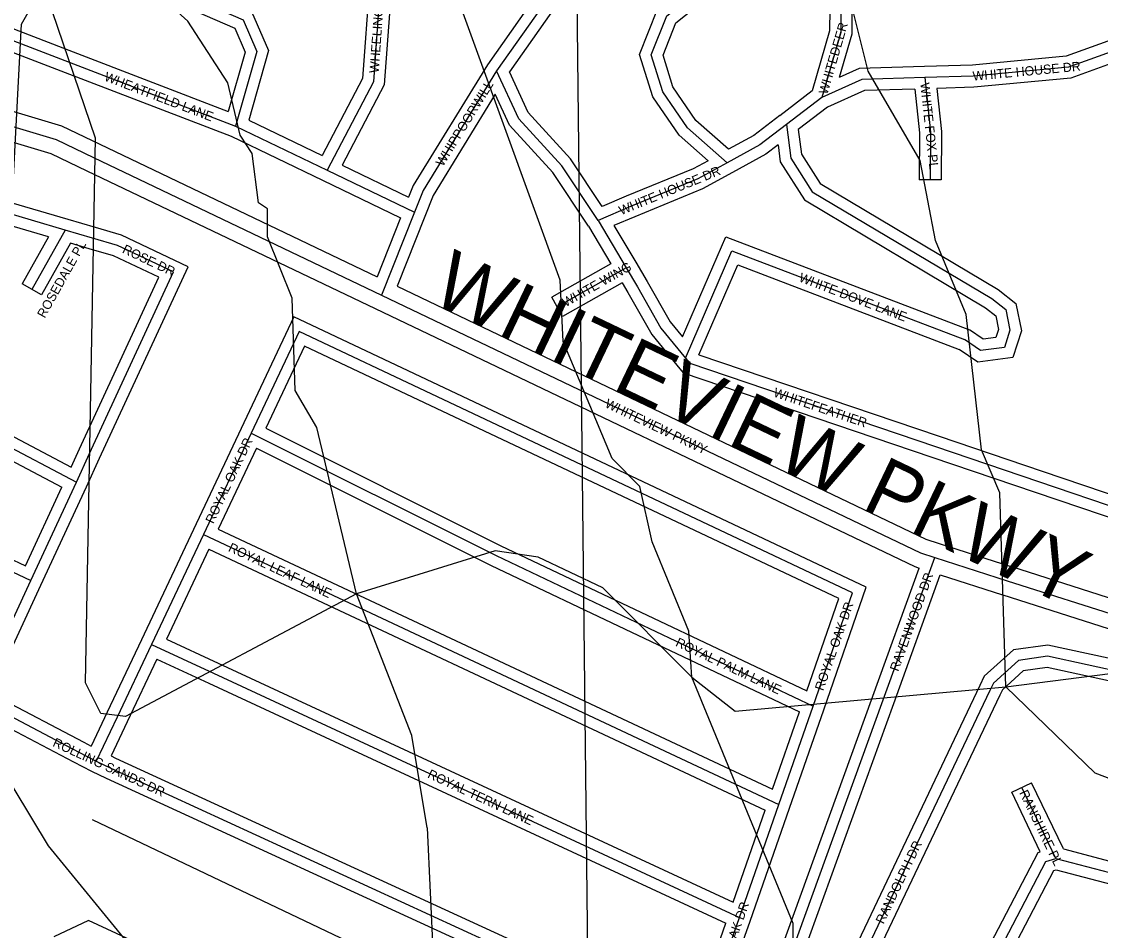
# Model space of a CAD drawing. Extents: x 457167 to 656239, y 1787309 to 1969297.
# Drawn here: x 578435 to 581357, y 1883556 to 1886017 of the extents above; entities that cross this region are included whole.
import ezdxf

# ---------------------------------------------------------------- set-up
doc = ezdxf.new("R2010")
doc.units = 0
for name, color, linetype in [('Level 1', 7, 'Continuous'), ('Level 22', 7, 'Continuous'), ('Level 23', 7, 'Continuous'), ('Level 28', 7, 'Continuous'), ('Level 31', 7, 'Continuous'), ('Level 32', 7, 'Continuous'), ('Level 34', 7, 'Continuous'), ('Level 5', 7, 'Continuous'), ('Level 7', 7, 'Continuous')]:
    doc.layers.add(name, color=color, linetype=linetype)

msp = doc.modelspace()

# ---------------------------------------------------------------- linework, layer by layer
at = {"layer": 'Level 1'}
msp.add_line((579922.889, 1887536.016), (579980.794, 1882300.366), dxfattribs=at)
at = {"layer": 'Level 22'}
for p, q in [((578629.542, 1885649.562), (579410.25, 1885276.297)), ((580908.17, 1884565.946), (581104.294, 1884503.001)), ((581104.294, 1884503.001), (581592.856, 1884347.106))]:
    msp.add_line(p, q, dxfattribs=at)
for points in [[(577109.898, 1886124.416), (578528.818, 1885697.774), (578629.542, 1885649.562)], [(579410.25, 1885276.297), (580869.39, 1884578.388), (580908.17, 1884565.946)]]:
    msp.add_lwpolyline(points, dxfattribs=at)
at = {"layer": 'Level 23'}
for p, q in [((578646.796, 1885685.651), (579397.924, 1885326.527)), ((578612.289, 1885613.474), (579392.997, 1885240.209)), ((580920.394, 1884604.032), (581116.517, 1884541.089)), ((581116.453, 1884541.11), (581605.016, 1884385.213)), ((580923.139, 1884519.131), (581092.07, 1884464.914)), ((581092.134, 1884464.893), (581580.698, 1884308.997))]:
    msp.add_line(p, q, dxfattribs=at)
for points in [[(577146.313, 1886155.236), (578543.298, 1885735.19), (578646.812, 1885685.643)], [(577102.36, 1886084.911), (578514.338, 1885660.358), (578612.273, 1885613.481)], [(579452.18, 1885300.582), (580884.199, 1884615.646), (580920.391, 1884604.034)], [(579392.991, 1885240.211), (580854.583, 1884541.13), (580865.97, 1884537.476)]]:
    msp.add_lwpolyline(points, dxfattribs=at)
at = {"layer": 'Level 31'}
for p, q in [((580024.011, 1886313.221), (579721.612, 1885884.022)), ((578564.242, 1885907.519), (579014.892, 1885734.576)), ((580602.173, 1885811.669), (580506.606, 1885738.773)), ((579014.892, 1885734.576), (579262.732, 1885614.787)), ((579262.732, 1885614.787), (579499.453, 1885500.841)), ((578553.114, 1885452.63), (578246.373, 1885542.73)), ((579499.453, 1885500.841), (579410.25, 1885276.297)), ((579996.223, 1885479.09), (580072.614, 1885350.568)), ((578553.114, 1885452.63), (578463.085, 1885292.091)), ((578626.86, 1885431.021), (578553.114, 1885452.63)), ((578619.282, 1884847.396), (578846.769, 1885339.288)), ((580072.614, 1885350.568), (579885.693, 1885245.133)), ((579186.765, 1885178.215), (579057.059, 1884902.846)), ((580685.644, 1884470.035), (579186.765, 1885178.215)), ((579057.059, 1884902.846), (578927.99, 1884628.568)), ((579057.059, 1884902.846), (579720.185, 1884570.924)), ((580910.051, 1884866.308), (581189.442, 1884771.559)), ((578583.496, 1884769.652), (578619.282, 1884847.396)), ((578460.484, 1884503.726), (578583.496, 1884769.652)), ((581189.442, 1884771.559), (581477.098, 1884673.886)), ((578927.99, 1884628.568), (578787.418, 1884329.95)), ((578927.99, 1884628.568), (579322.65, 1884443.018)), ((579720.185, 1884570.924), (580099.594, 1884390.869)), ((580768.71, 1884180.409), (580908.17, 1884565.946)), ((578312.549, 1884184.761), (578460.484, 1884503.726)), ((580579.103, 1884163.34), (580685.644, 1884470.035)), ((579322.65, 1884443.018), (580486.319, 1883896.982)), ((580099.594, 1884390.869), (580579.103, 1884163.34)), ((578787.418, 1884329.95), (578694.45, 1884133.779)), ((578787.418, 1884329.95), (578954.564, 1884252.51)), ((578954.564, 1884252.51), (580379.777, 1883591.016)), ((578312.549, 1884184.761), (578589.924, 1884039.087)), ((580465.153, 1883342.84), (580768.71, 1884180.409)), ((580486.319, 1883896.982), (580579.103, 1884163.34)), ((578694.45, 1884133.779), (578637.582, 1884013.896)), ((578589.924, 1884039.087), (578637.582, 1884013.896)), ((578637.582, 1884013.896), (578676.986, 1883995.632)), ((578676.986, 1883995.632), (580265.558, 1883265.43)), ((581235.733, 1883751.094), (581143.559, 1883942.918)), ((580379.777, 1883591.016), (580486.319, 1883896.982)), ((581235.733, 1883751.094), (581870.919, 1883583.996)), ((580318.989, 1883418.048), (580379.777, 1883591.016))]:
    msp.add_line(p, q, dxfattribs=at)
for points in [[(577879.429, 1886195.146), (577932.779, 1886155.396), (577988.45, 1886160.732), (578387.86, 1885975.162), (578564.242, 1885907.519)], [(578645.304, 1886192.08), (579035.208, 1886022.173), (579072.244, 1885936.641), (579014.892, 1885734.576)], [(580346.093, 1885635.101), (580238.462, 1885729.503), (580171.869, 1885827.095), (580140.586, 1885927.524), (580182.467, 1886032.893), (580294.607, 1886122.846), (580409.238, 1886186.611), (580467.765, 1886189.037), (580579.053, 1886173.174), (580654.66, 1886128.656), (580653.419, 1885987.566), (580602.173, 1885811.669)], [(579408.533, 1886139.216), (579387.907, 1885854.53), (579262.732, 1885614.787)], [(581522.66, 1885980.713), (581475.88, 1885968.443), (581270.264, 1885893.949), (581012.269, 1885869.745), (580880.903, 1885865.647)], [(579721.612, 1885884.022), (579522.793, 1885559.702), (579499.453, 1885500.841)], [(579996.223, 1885479.09), (579897.926, 1885626.93), (579782.094, 1885754.078), (579721.612, 1885884.022)], [(580880.903, 1885865.647), (580710.73, 1885860.539), (580602.173, 1885811.669)], [(580880.903, 1885865.647), (580896.825, 1885717.977), (580895.609, 1885588.888)], [(580506.606, 1885738.773), (580434.294, 1885684.011), (580346.093, 1885635.101)], [(580506.606, 1885738.773), (580518.825, 1885647.838), (580576.527, 1885556.447), (581062.579, 1885267.092), (581100.368, 1885237.197), (581111.706, 1885181.537), (581096.662, 1885134.659), (581032.078, 1885126.426), (580988.563, 1885155.969)], [(580346.093, 1885635.101), (580266.487, 1885591.263), (580084.403, 1885516.727), (579996.223, 1885479.09)], [(578846.769, 1885339.288), (578695.203, 1885411.241), (578626.86, 1885431.021)], [(580232.736, 1885106.237), (580358.329, 1885396.528), (580988.563, 1885155.969)], [(580072.614, 1885350.568), (580103.041, 1885298.868), (580166.425, 1885186.738), (580232.736, 1885106.237)], [(576976.576, 1885202.511), (577734.242, 1885217.989), (578583.496, 1884769.652)], [(580232.736, 1885106.237), (580244.476, 1885092.031), (580910.051, 1884866.308)], [(576991.504, 1884893.021), (577643.854, 1884889.087), (578460.484, 1884503.726)], [(581428.539, 1884251.436), (581213.616, 1884298.416), (581134.711, 1884287.302), (581066.837, 1884225.985), (581057.574, 1884206.003)], [(581057.574, 1884206.003), (580549.346, 1883137.939), (580555.006, 1883105.564), (580566.367, 1883061.541), (580699.668, 1882916.177), (580763.226, 1882886.956)], [(580763.226, 1882886.956), (581209.315, 1883742.421), (581235.733, 1883751.094)]]:
    msp.add_lwpolyline(points, dxfattribs=at)
at = {"layer": 'Level 32'}
for p, q in [((579987.384, 1886313.321), (579696.536, 1885900.518)), ((580046.989, 1886293.744), (579756.139, 1885880.937)), ((578574.991, 1885935.527), (578994.995, 1885774.345)), ((578553.494, 1885879.511), (579002.97, 1885707.017)), ((580576.132, 1885829.536), (580488.412, 1885762.626)), ((580617.629, 1885785.726), (580538.661, 1885725.491)), ((579050.633, 1885750.622), (579249.601, 1885654.455)), ((579002.969, 1885707.017), (579249.677, 1885587.776)), ((579303.671, 1885628.376), (579483.439, 1885541.845)), ((578561.569, 1885481.414), (578254.827, 1885571.514)), ((579249.721, 1885587.755), (579461.251, 1885485.935)), ((580925.608, 1885588.605), (580865.61, 1885589.171)), ((578508.529, 1885434.457), (578260.597, 1885507.283)), ((578635.296, 1885459.811), (578561.551, 1885481.42)), ((579461.251, 1885485.935), (579397.924, 1885326.528)), ((579527.334, 1885489.765), (579452.18, 1885300.582)), ((579970.822, 1885463.109), (580031.145, 1885361.621)), ((580039.526, 1885464.952), (580098.403, 1885365.896)), ((578508.529, 1885434.457), (578436.919, 1885306.765)), ((578567.6, 1885417.122), (578489.253, 1885277.416)), ((578618.424, 1885402.23), (578567.599, 1885417.122)), ((580031.144, 1885361.62), (579870.954, 1885271.263)), ((578646.512, 1884834.802), (578886.466, 1885353.651)), ((578489.253, 1885277.416), (578436.919, 1885306.765)), ((578592.053, 1884859.988), (578807.074, 1885324.922)), ((580061.699, 1885309.966), (579900.433, 1885219.003)), ((579900.433, 1885219.003), (579870.954, 1885271.263)), ((579172.424, 1885218.17), (579029.92, 1884915.63)), ((580722.827, 1884485.646), (579172.424, 1885218.171)), ((579201.108, 1885138.258), (579096.683, 1884916.561)), ((580648.464, 1884454.421), (579201.108, 1885138.257)), ((580269.339, 1885115.279), (580919.685, 1884894.72)), ((579029.915, 1884915.62), (578900.845, 1884641.341)), ((579096.684, 1884916.561), (579733.333, 1884597.892)), ((580919.685, 1884894.719), (581199.076, 1884799.97)), ((578569.49, 1884810.971), (578592.03, 1884859.94)), ((579071.118, 1884862.26), (578967.914, 1884642.948)), ((579071.119, 1884862.259), (579707.039, 1884543.954)), ((578610.748, 1884757.106), (578646.534, 1884834.851)), ((580900.417, 1884837.896), (581179.808, 1884743.147)), ((581199.087, 1884799.966), (581486.744, 1884702.294)), ((578445.948, 1884543.757), (578544.317, 1884756.411)), ((578487.712, 1884491.13), (578610.724, 1884757.056)), ((581179.797, 1884743.151), (581467.453, 1884645.478)), ((578900.847, 1884641.346), (578760.274, 1884342.727)), ((578967.914, 1884642.947), (579335.415, 1884470.167)), ((579733.333, 1884597.892), (580112.456, 1884417.972)), ((578942.364, 1884588.658), (578827.418, 1884344.481)), ((578942.363, 1884588.66), (579309.886, 1884415.868)), ((579707.039, 1884543.954), (580086.733, 1884363.765)), ((580740.499, 1884190.614), (580865.97, 1884537.476)), ((580796.923, 1884170.203), (580923.14, 1884519.131)), ((578351.781, 1884198.043), (578487.699, 1884491.102)), ((580607.443, 1884153.495), (580722.828, 1884485.647)), ((579335.394, 1884470.177), (580468.937, 1883938.277)), ((580561.742, 1884204.783), (580648.463, 1884454.421)), ((579309.908, 1884415.858), (580449.095, 1883881.309)), ((580112.454, 1884417.973), (580561.741, 1884204.784)), ((580086.734, 1884363.764), (580541.915, 1884147.779)), ((578760.308, 1884342.797), (578667.34, 1884146.626)), ((578827.417, 1884344.481), (578967.175, 1884279.731)), ((578801.792, 1884290.226), (578721.56, 1884120.931)), ((578801.793, 1884290.226), (578941.953, 1884225.288)), ((578967.194, 1884279.722), (580362.345, 1883632.181)), ((578941.934, 1884225.296), (580342.444, 1883575.268)), ((578351.78, 1884198.043), (578603.873, 1884065.647)), ((580436.949, 1883353.062), (580740.505, 1884190.631)), ((580493.359, 1883332.616), (580796.916, 1884170.186)), ((578326.471, 1884143.563), (578575.975, 1884012.527)), ((578667.345, 1884146.636), (578623.905, 1884055.059)), ((580468.937, 1883938.277), (580541.914, 1884147.779)), ((580514.65, 1883887.113), (580607.434, 1884153.471)), ((578721.555, 1884120.921), (578677.661, 1884028.386)), ((578603.944, 1884065.611), (578623.905, 1884055.06)), ((578575.904, 1884012.563), (578624.257, 1883987.006)), ((578677.662, 1884028.386), (578689.603, 1884022.851)), ((578689.603, 1884022.851), (580248.136, 1883306.456)), ((578624.257, 1883987.006), (578664.371, 1883968.413)), ((578664.458, 1883968.373), (580253.029, 1883238.171)), ((581116.519, 1883929.925), (581170.599, 1883955.911)), ((581256.771, 1883776.581), (581170.599, 1883955.911)), ((581193.879, 1883768.928), (581116.519, 1883929.925)), ((580362.345, 1883632.181), (580449.095, 1883881.31)), ((580408.109, 1883581.149), (580514.651, 1883887.116)), ((581256.771, 1883776.581), (581848.923, 1883620.803)), ((581236.671, 1883719.826), (581834.866, 1883562.459)), ((580290.686, 1883427.995), (580342.444, 1883575.268)), ((580347.293, 1883408.101), (580408.081, 1883581.068))]:
    msp.add_line(p, q, dxfattribs=at)
for points in [[(578692.586, 1886204.201), (579058.037, 1886044.951), (579104.026, 1885938.743), (579050.632, 1885750.622)], [(580294.157, 1885640.747), (580215.823, 1885709.454), (580144.559, 1885813.891), (580108.785, 1885928.739), (580157.514, 1886051.338), (580277.81, 1886147.832), (580400.878, 1886216.291), (580469.273, 1886219.126), (580589.161, 1886202.037), (580684.812, 1886145.717), (580683.383, 1885983.156), (580649.17, 1885865.726)], [(577920.014, 1886202.319), (577941.429, 1886186.363), (577993.7, 1886191.374), (578399.565, 1886002.805), (578574.984, 1885935.531)], [(577861.505, 1886171.088), (577924.129, 1886124.428), (577983.201, 1886130.091), (578376.155, 1885947.52), (578553.499, 1885879.508)], [(578633.319, 1886164.576), (579012.379, 1885999.396), (579040.462, 1885934.539), (578994.995, 1885774.346)], [(580350.005, 1885671.574), (580261.101, 1885749.551), (580199.178, 1885840.3), (580172.386, 1885926.309), (580207.419, 1886014.449), (580311.404, 1886097.86), (580417.598, 1886156.931), (580466.257, 1886158.949), (580568.944, 1886144.311), (580624.509, 1886111.594), (580623.457, 1885991.977), (580576.131, 1885829.536)], [(579377.122, 1886120.817), (579358.434, 1885862.901), (579249.601, 1885654.455)], [(579438.454, 1886137.049), (579417.379, 1885846.158), (579303.671, 1885628.376)], [(581515.049, 1886009.732), (581466.947, 1885997.116), (581263.648, 1885923.461), (581010.399, 1885899.701), (580879.968, 1885895.633)], [(581504.637, 1885944.969), (581484.814, 1885939.771), (581276.882, 1885864.437), (581014.14, 1885839.787), (580914.203, 1885836.67)], [(579696.536, 1885900.517), (579495.86, 1885573.172), (579483.44, 1885541.846)], [(580880.003, 1885895.634), (580703.861, 1885890.347), (580649.171, 1885865.726)], [(580007.393, 1885516.476), (579921.643, 1885645.443), (579807.359, 1885770.893), (579756.139, 1885880.937)], [(580854.052, 1885834.826), (580717.6, 1885830.731), (580617.629, 1885785.726)], [(580854.053, 1885834.826), (580866.809, 1885716.506), (580865.61, 1885589.171)], [(580914.202, 1885836.669), (580926.84, 1885719.45), (580925.608, 1885588.605)], [(579717.99, 1885820.711), (579549.725, 1885546.233), (579527.341, 1885489.783)], [(579970.822, 1885463.109), (579874.209, 1885608.416), (579756.83, 1885737.262), (579717.99, 1885820.711)], [(580488.494, 1885762.689), (580417.882, 1885709.214), (580350.004, 1885671.574)], [(580538.661, 1885725.491), (580547.687, 1885658.321), (580598.054, 1885578.546), (581079.633, 1885291.854), (581127.576, 1885253.925), (581142.668, 1885179.839), (581119.394, 1885107.313), (581024.616, 1885095.231), (580974.602, 1885129.185)], [(580483.722, 1885683.809), (580450.708, 1885658.808), (580360.641, 1885608.863)], [(580483.722, 1885683.809), (580489.964, 1885637.356), (580555, 1885534.348), (581045.524, 1885242.331), (581073.159, 1885220.469), (581080.744, 1885183.236), (581073.93, 1885162.004), (581039.54, 1885157.621), (581002.525, 1885182.751)], [(580294.157, 1885640.747), (580253.525, 1885618.375), (580072.83, 1885544.406), (580007.393, 1885516.476)], [(580360.564, 1885608.821), (580279.449, 1885564.151), (580095.975, 1885489.047), (580039.525, 1885464.952)], [(578886.467, 1885353.651), (578705.875, 1885439.385), (578635.199, 1885459.839)], [(580224.689, 1885163.191), (580342.197, 1885434.797), (581002.524, 1885182.751)], [(578807.074, 1885324.922), (578684.531, 1885383.098), (578618.52, 1885402.202)], [(580098.468, 1885365.785), (580129.029, 1885313.86), (580191.25, 1885203.786), (580224.689, 1885163.19)], [(580269.339, 1885115.279), (580374.46, 1885358.259), (580974.603, 1885129.185)], [(580061.699, 1885309.966), (580077.054, 1885283.877), (580141.6, 1885169.69), (580209.58, 1885087.162)], [(577005.13, 1885233.1), (577741.386, 1885248.142), (578569.489, 1884810.97)], [(577008.029, 1885173.146), (577727.098, 1885187.836), (578544.317, 1884756.411)], [(580209.611, 1885087.126), (580226.776, 1885066.355), (580900.416, 1884837.896)], [(577020.101, 1884922.85), (577650.662, 1884919.047), (578445.948, 1884543.758)], [(581436.484, 1884280.407), (581214.763, 1884328.874), (581121.422, 1884315.728), (581042.191, 1884244.15), (581030.484, 1884218.894)], [(581420.595, 1884222.462), (581212.469, 1884267.957), (581147.999, 1884258.877), (581091.484, 1884207.821), (581084.664, 1884193.112)], [(581030.484, 1884218.894), (580518.147, 1883142.194), (580525.659, 1883099.223), (580539.191, 1883046.788), (580681.643, 1882891.445), (580750.694, 1882859.698)], [(581084.664, 1884193.112), (580580.545, 1883133.684), (580584.353, 1883111.906), (580593.544, 1883076.294), (580717.693, 1882940.91), (580749.824, 1882926.136)], [(580749.824, 1882926.136), (581188.359, 1883767.116), (581193.88, 1883768.928)], [(580804.394, 1882901.017), (581230.271, 1883717.725), (581236.672, 1883719.826)], [(579953.198, 1882660.94), (580066.543, 1882909.31), (578616.13, 1883582.342), (578522.548, 1883538.048)]]:
    msp.add_lwpolyline(points, dxfattribs=at)
at = {"layer": 'Level 5'}
msp.add_line((580333.494, 1883043.834), (578627.391, 1883855.007), dxfattribs=at)
for points in [[(579342.236, 1884467.606), (578716.652, 1884134.835), (578649.961, 1884143.235), (578608.379, 1884226.636), (578634.95, 1885702.142), (578518.594, 1886044.06), (578468.613, 1886069.131)], [(580250.662, 1884241.546), (580009.165, 1884483.56), (579834.172, 1884567.121), (579717.49, 1884583.921), (579342.236, 1884467.606)], [(581100.924, 1884215.649), (581426.079, 1884256.971), (581559.519, 1884323.534), (581776.49, 1884531.68)], [(580250.662, 1884241.546), (580367.275, 1884149.744), (581100.924, 1884215.649)]]:
    msp.add_lwpolyline(points, dxfattribs=at)
at = {"layer": 'Level 7'}
for points in [[(581100.924, 1884215.649), (581084.807, 1884740.841), (581034.915, 1884857.614), (580993.629, 1885224.453), (580910.456, 1885424.617), (580869.002, 1885641.402), (580727.547, 1885883.317), (580578.137, 1886483.701), (580544.866, 1886533.752), (580486.86, 1886867.27), (580512.582, 1887542.486), (580571.071, 1887667.46), (580712.912, 1887784.043), (580954.605, 1887742.094), (581062.879, 1887641.931), (581312.606, 1887291.545), (581379.139, 1887149.761)], [(580250.662, 1884241.546), (580242.45, 1884366.618), (580142.676, 1884608.473), (580109.494, 1884758.557), (580034.531, 1884833.658), (579901.475, 1885150.596), (579893.333, 1885317.33), (579594.108, 1886142.958), (579585.866, 1886234.65), (579452.781, 1886501.576), (579436.229, 1886634.959), (579236.877, 1887302.104), (579212.094, 1887527.209), (579112.151, 1887627.351), (578928.759, 1887602.54), (578870.339, 1887569.259), (578528.484, 1887502.926), (578003.396, 1887586.845)], [(579342.236, 1884467.606), (579234.349, 1884917.896), (579176.087, 1885017.998), (579168.014, 1885268.095), (579101.52, 1885434.888), (579101.579, 1885509.91), (579076.609, 1885526.621), (579060.066, 1885660.003), (579026.785, 1885710.085), (578993.563, 1885851.838), (578885.389, 1886018.661), (578793.757, 1886102.123), (578468.613, 1886069.131)], [(579533.288, 1883833.841), (579549.602, 1883483.683), (579390.854, 1883158.735), (579265.714, 1883067.191), (579149.002, 1883075.631), (579040.699, 1883134.112), (578507.894, 1883784.906), (578366.399, 1884018.49), (578341.585, 1884201.925), (578359.066, 1884968.833), (578384.175, 1885043.865), (578435.203, 1886010.809), (578468.613, 1886069.131)], [(579533.288, 1883833.841), (579491.864, 1884083.967), (579342.236, 1884467.606)], [(580524.749, 1883315.914), (580525.045, 1883574.341), (580250.662, 1884241.546)], [(581466.327, 1882906.419), (581483.234, 1883123.165), (581700.393, 1883514.745), (581692.349, 1883789.841), (581584.076, 1883890.014), (581342.421, 1883981.975), (581100.924, 1884215.649)]]:
    msp.add_lwpolyline(points, dxfattribs=at)

# ---------------------------------------------------------------- texts
at = {"layer": 'Level 28'}
msp.add_text('WHITEVIEW PKWY', height=160, rotation=334.438, dxfattribs=at).set_placement((579536.916, 1885258.367))
at = {"layer": 'Level 34'}
for s, rotation, p in [('WHEELING LANE', 85.855389, (579402.082, 1885877.226)), ('WHITEDEER', 73.755864, (580617.199, 1885818.558)), ('WHITE HOUSE DR', 5.359403, (581012.14, 1885857.179)), ('WHEATFIELD LANE', 339.004867, (578657.175, 1885858.466)), ('WHITE FOX PL', 276.153325, (580868.738, 1885850.555)), ('WHIPPOORWILL', 58.489261, (579576.314, 1885623.093)), ('WHITE HOUSE DR', 22.261181, (580059.069, 1885492.851)), ('ROSEDALE PL', 60.715764, (578497.654, 1885212.521)), ('ROSE DR', 334.604658, (578705.875, 1885392.338)), ('WHITE WING', 29.425058, (579908.755, 1885243.791)), ('WHITE DOVE LANE', 339.108103, (580538.339, 1885314.439)), ('WHITEFEATHER', 341.265942, (580469.449, 1885002.535)), ('WHITEVIEW PKWY', 334.438, (580012.96, 1884974.165)), ('ROYAL OAK DR', 64.798511, (578954.549, 1884655.653)), ('ROYAL LEAF LANE', 334.819292, (578993.021, 1884584.181)), ('RAVENWOOD DR', 70.112533, (580809.214, 1884255.637)), ('ROYAL OAK DR', 70.842611, (580606.197, 1884203.247)), ('ROYAL PALM LANE', 334.615358, (580204.234, 1884327.381)), ('ROLLING SANDS DR', 335.131, (578517.437, 1884055.811)), ('ROYAL TERN LANE', 335.102119, (579532.49, 1883970.492)), ('RANSHIRE PL', 295.664392, (581136.434, 1883928.888)), ('RANDOLPH DR', 64.552164, (580769.478, 1883571.468)), ('ROYAL OAK DR', 70.6356, (580322.796, 1883391.187))]:
    msp.add_text(s, height=25, rotation=rotation, dxfattribs=at).set_placement(p)

doc.saveas('drawing.dxf')
